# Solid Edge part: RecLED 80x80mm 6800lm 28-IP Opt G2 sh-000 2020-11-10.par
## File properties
Author: sylwester.cabaj
Template: iso metric part.par
Last saved by: sylwester.cabaj
Revision: 1
Application: Solid Edge
Gęstość: 0.000 kg/m^3
Dokładność: 0.990
Username: sylwester.cabaj
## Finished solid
Body 1: solid body, 1482 faces, 3857 edges, 2429 vertices.
  Faces by surface: plane 697, cylinder 595, spline 80, torus 67, cone 26, sphere 10, spun 7
  Edges by curve: line 2412, circle 941, curve on surface 282, ellipse 178, spline 38, intersection 6
Bounding box of the edges (mm; curved faces can reach further): 80.000 x 4.950 x 80.000, from (-40, -3.45, -40) to (40, 1.5, 40).
Cylindrical faces by radius (mm): R0.05 x112, R0.1 x336, R0.2 x67, R0.2002 x2, R0.2169 x3, R0.25 x12, R0.3 x2, R0.3373 x3, R0.4 x8, R0.4006 x2, R0.4008 x2, R0.525 x2, R0.6 x12, R1 x7, R1.0894 x2, R1.1 x18, R1.75 x4, R4 x1
Conical faces (half-angle, radius in mm at the cone's reference point): 0.5 deg R0.5056 x4, 0.5 deg R1.0082 x4, 1 deg R0.5511 x2, 10 deg R0.2132 x2, 10 deg R0.4132 x2, 18.4844 deg R1.0657 x4, 27.363 deg R0.6214 x2, 45 deg R0.575 x2, 45 deg R0.625 x4
Toroidal faces (ring radius, tube radius in mm): R-0.0731 r1.395 x28, R0.1 r0.2 x1, R0.8 r0.2 x4, R0.8522 r0.3 x2, R0.9002 r0.2 x1, R0.9018 r0.2 x1, R1.3 r0.2 x2, R1.4708 r0.15 x28
Spherical faces by radius (mm): R0.2 x8, R0.6 x2
Planar faces by outward normal: +x 113, +y 36, +z 113, -x 141, -y 48, -z 113, oblique 133
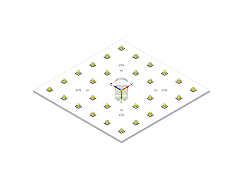
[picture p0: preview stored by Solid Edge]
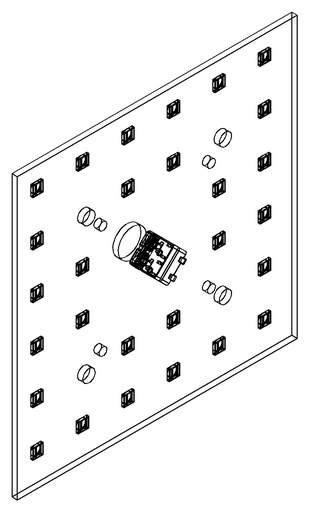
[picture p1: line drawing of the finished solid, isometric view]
